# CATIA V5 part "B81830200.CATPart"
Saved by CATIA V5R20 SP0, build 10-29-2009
Part number: B81830200
Revision: 3
Definition: design
Nomenclature: B81830200
Source: made
Description: NOT SPECIFIED
Bounding box of the stored display mesh (mm): x -17.817 to 17.817, y -18 to 18, z 0 to 200
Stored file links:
  C:\Users\Raffaele\Desktop\3D X SITO CF\BOLEX\6-PILLAR REF 818\B81830200.CATPart
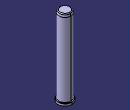
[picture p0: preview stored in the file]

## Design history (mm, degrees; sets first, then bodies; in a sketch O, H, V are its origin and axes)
Body1 "MANIFOLD_SOLID_BREP #370" (main body)
  Solid1: solid without history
